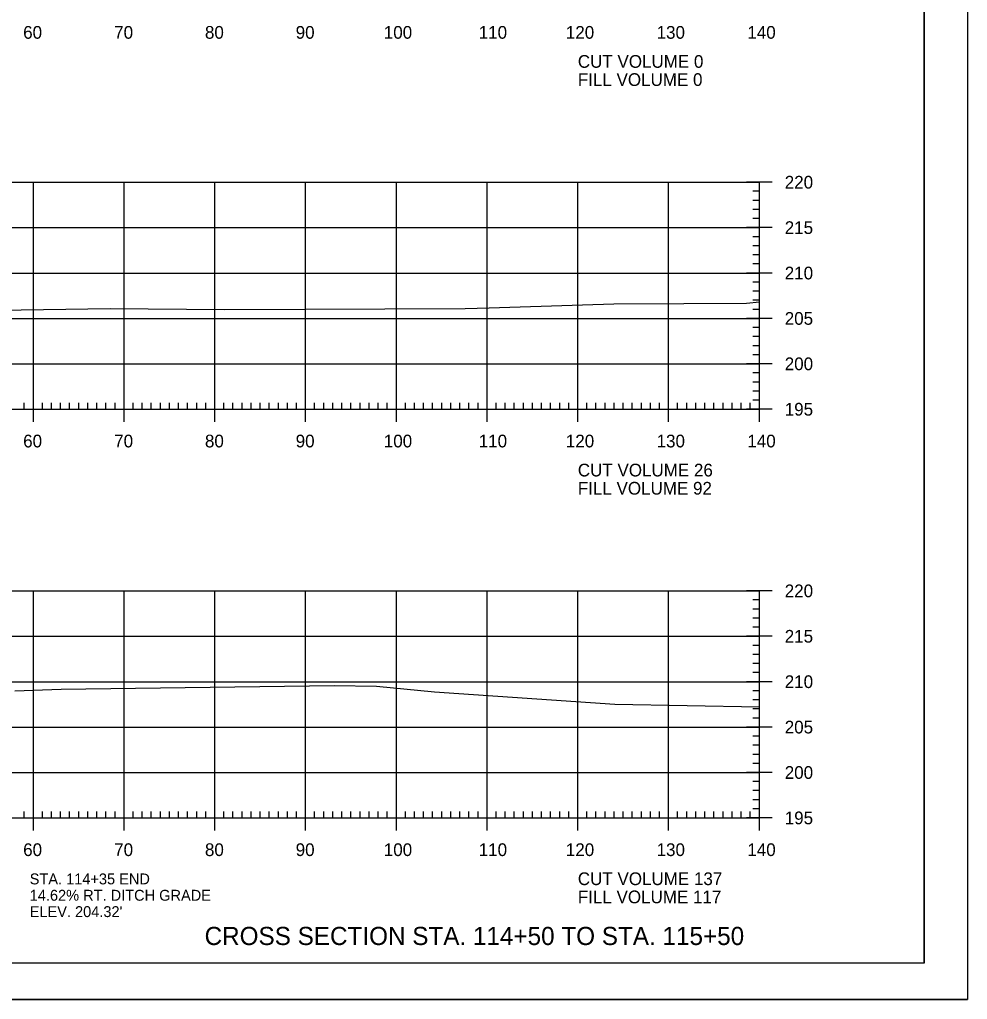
# Model space of a CAD drawing. Extents: x 1312042 to 1371461, y 379929 to 1834241.
# Drawn here: x 1371356.8 to 1371461.2, y 380142.3 to 380250.2 of the extents above; entities that cross this region are included whole.
import ezdxf

# ---------------------------------------------------------------- set-up
doc = ezdxf.new("R2010")
doc.units = 0
for name, color, linetype in [('R_Axis', 7, 'Continuous'), ('R_Axis Annot', 7, 'Continuous'), ('R_Border', 7, 'Continuous'), ('R_Draft', 7, 'Continuous'), ('R_Drive', 7, 'Continuous'), ('R_Exist Surface', 7, 'Continuous'), ('R_Grid', 7, 'Continuous'), ('R_No Plot', 7, 'Continuous')]:
    doc.layers.add(name, color=color, linetype=linetype)

msp = doc.modelspace()

# ---------------------------------------------------------------- linework, layer by layer
at = {"layer": 'R_Axis'}
for p, q in [((1371439.68, 380232.25), (1371436.88, 380232.25)), ((1371438.28, 380207.25), (1371438.28, 380232.25)), ((1371438.28, 380231.25), (1371437.58, 380231.25)), ((1371438.28, 380230.25), (1371437.58, 380230.25)), ((1371438.28, 380229.25), (1371437.58, 380229.25)), ((1371438.28, 380228.25), (1371437.58, 380228.25)), ((1371439.68, 380227.25), (1371436.88, 380227.25)), ((1371438.28, 380226.25), (1371437.58, 380226.25)), ((1371438.28, 380225.25), (1371437.58, 380225.25)), ((1371438.28, 380224.25), (1371437.58, 380224.25)), ((1371438.28, 380223.25), (1371437.58, 380223.25)), ((1371439.68, 380222.25), (1371436.88, 380222.25)), ((1371438.28, 380221.25), (1371437.58, 380221.25)), ((1371438.28, 380220.25), (1371437.58, 380220.25)), ((1371438.28, 380219.25), (1371437.58, 380219.25)), ((1371438.28, 380218.25), (1371437.58, 380218.25)), ((1371439.68, 380217.25), (1371436.88, 380217.25)), ((1371438.28, 380216.25), (1371437.58, 380216.25)), ((1371438.28, 380215.25), (1371437.58, 380215.25)), ((1371438.28, 380214.25), (1371437.58, 380214.25)), ((1371438.28, 380213.25), (1371437.58, 380213.25)), ((1371439.68, 380212.25), (1371436.88, 380212.25)), ((1371438.28, 380211.25), (1371437.58, 380211.25)), ((1371438.28, 380210.25), (1371437.58, 380210.25)), ((1371438.28, 380209.25), (1371437.58, 380209.25)), ((1371357.28, 380207.25), (1371357.28, 380207.95)), ((1371358.28, 380205.85), (1371358.28, 380208.65)), ((1371359.28, 380207.25), (1371359.28, 380207.95)), ((1371360.28, 380207.25), (1371360.28, 380207.95)), ((1371361.28, 380207.25), (1371361.28, 380207.95)), ((1371362.28, 380207.25), (1371362.28, 380207.95)), ((1371363.28, 380207.25), (1371363.28, 380207.95)), ((1371364.28, 380207.25), (1371364.28, 380207.95)), ((1371365.28, 380207.25), (1371365.28, 380207.95)), ((1371366.28, 380207.25), (1371366.28, 380207.95)), ((1371367.28, 380207.25), (1371367.28, 380207.95)), ((1371368.28, 380205.85), (1371368.28, 380208.65)), ((1371369.28, 380207.25), (1371369.28, 380207.95)), ((1371370.28, 380207.25), (1371370.28, 380207.95)), ((1371371.28, 380207.25), (1371371.28, 380207.95)), ((1371372.28, 380207.25), (1371372.28, 380207.95)), ((1371373.28, 380207.25), (1371373.28, 380207.95)), ((1371374.28, 380207.25), (1371374.28, 380207.95)), ((1371375.28, 380207.25), (1371375.28, 380207.95)), ((1371376.28, 380207.25), (1371376.28, 380207.95)), ((1371377.28, 380207.25), (1371377.28, 380207.95)), ((1371378.28, 380205.85), (1371378.28, 380208.65)), ((1371379.28, 380207.25), (1371379.28, 380207.95)), ((1371380.28, 380207.25), (1371380.28, 380207.95)), ((1371381.28, 380207.25), (1371381.28, 380207.95)), ((1371382.28, 380207.25), (1371382.28, 380207.95)), ((1371383.28, 380207.25), (1371383.28, 380207.95)), ((1371384.28, 380207.25), (1371384.28, 380207.95)), ((1371385.28, 380207.25), (1371385.28, 380207.95)), ((1371386.28, 380207.25), (1371386.28, 380207.95)), ((1371387.28, 380207.25), (1371387.28, 380207.95)), ((1371388.28, 380205.85), (1371388.28, 380208.65)), ((1371389.28, 380207.25), (1371389.28, 380207.95)), ((1371390.28, 380207.25), (1371390.28, 380207.95)), ((1371391.28, 380207.25), (1371391.28, 380207.95)), ((1371392.28, 380207.25), (1371392.28, 380207.95)), ((1371393.28, 380207.25), (1371393.28, 380207.95)), ((1371394.28, 380207.25), (1371394.28, 380207.95)), ((1371395.28, 380207.25), (1371395.28, 380207.95)), ((1371396.28, 380207.25), (1371396.28, 380207.95)), ((1371397.28, 380207.25), (1371397.28, 380207.95)), ((1371398.28, 380205.85), (1371398.28, 380208.65)), ((1371399.28, 380207.25), (1371399.28, 380207.95)), ((1371400.28, 380207.25), (1371400.28, 380207.95)), ((1371401.28, 380207.25), (1371401.28, 380207.95)), ((1371402.28, 380207.25), (1371402.28, 380207.95)), ((1371403.28, 380207.25), (1371403.28, 380207.95)), ((1371404.28, 380207.25), (1371404.28, 380207.95)), ((1371405.28, 380207.25), (1371405.28, 380207.95)), ((1371406.28, 380207.25), (1371406.28, 380207.95)), ((1371407.28, 380207.25), (1371407.28, 380207.95)), ((1371408.28, 380205.85), (1371408.28, 380208.65)), ((1371409.28, 380207.25), (1371409.28, 380207.95)), ((1371410.28, 380207.25), (1371410.28, 380207.95)), ((1371411.28, 380207.25), (1371411.28, 380207.95)), ((1371412.28, 380207.25), (1371412.28, 380207.95)), ((1371413.28, 380207.25), (1371413.28, 380207.95)), ((1371414.28, 380207.25), (1371414.28, 380207.95)), ((1371415.28, 380207.25), (1371415.28, 380207.95)), ((1371416.28, 380207.25), (1371416.28, 380207.95)), ((1371417.28, 380207.25), (1371417.28, 380207.95)), ((1371418.28, 380205.85), (1371418.28, 380208.65)), ((1371419.28, 380207.25), (1371419.28, 380207.95)), ((1371420.28, 380207.25), (1371420.28, 380207.95)), ((1371421.28, 380207.25), (1371421.28, 380207.95)), ((1371422.28, 380207.25), (1371422.28, 380207.95)), ((1371423.28, 380207.25), (1371423.28, 380207.95)), ((1371424.28, 380207.25), (1371424.28, 380207.95)), ((1371425.28, 380207.25), (1371425.28, 380207.95)), ((1371426.28, 380207.25), (1371426.28, 380207.95)), ((1371427.28, 380207.25), (1371427.28, 380207.95)), ((1371428.28, 380205.85), (1371428.28, 380208.65)), ((1371429.28, 380207.25), (1371429.28, 380207.95)), ((1371430.28, 380207.25), (1371430.28, 380207.95)), ((1371431.28, 380207.25), (1371431.28, 380207.95)), ((1371432.28, 380207.25), (1371432.28, 380207.95)), ((1371433.28, 380207.25), (1371433.28, 380207.95)), ((1371434.28, 380207.25), (1371434.28, 380207.95)), ((1371435.28, 380207.25), (1371435.28, 380207.95)), ((1371436.28, 380207.25), (1371436.28, 380207.95)), ((1371437.28, 380207.25), (1371437.28, 380207.95)), ((1371438.28, 380208.25), (1371437.58, 380208.25)), ((1371438.28, 380205.85), (1371438.28, 380208.65)), ((1371158.28, 380207.25), (1371438.28, 380207.25)), ((1371439.68, 380207.25), (1371436.88, 380207.25)), ((1371439.68, 380187.25), (1371436.88, 380187.25)), ((1371438.28, 380162.25), (1371438.28, 380187.25)), ((1371438.28, 380186.25), (1371437.58, 380186.25)), ((1371438.28, 380185.25), (1371437.58, 380185.25)), ((1371438.28, 380184.25), (1371437.58, 380184.25)), ((1371438.28, 380183.25), (1371437.58, 380183.25)), ((1371439.68, 380182.25), (1371436.88, 380182.25)), ((1371438.28, 380181.25), (1371437.58, 380181.25)), ((1371438.28, 380180.25), (1371437.58, 380180.25)), ((1371438.28, 380179.25), (1371437.58, 380179.25)), ((1371438.28, 380178.25), (1371437.58, 380178.25)), ((1371439.68, 380177.25), (1371436.88, 380177.25)), ((1371438.28, 380176.25), (1371437.58, 380176.25)), ((1371438.28, 380175.25), (1371437.58, 380175.25)), ((1371438.28, 380174.25), (1371437.58, 380174.25)), ((1371438.28, 380173.25), (1371437.58, 380173.25)), ((1371439.68, 380172.25), (1371436.88, 380172.25)), ((1371438.28, 380171.25), (1371437.58, 380171.25)), ((1371438.28, 380170.25), (1371437.58, 380170.25)), ((1371438.28, 380169.25), (1371437.58, 380169.25)), ((1371438.28, 380168.25), (1371437.58, 380168.25)), ((1371439.68, 380167.25), (1371436.88, 380167.25)), ((1371438.28, 380166.25), (1371437.58, 380166.25)), ((1371438.28, 380165.25), (1371437.58, 380165.25)), ((1371358.28, 380160.85), (1371358.28, 380163.65)), ((1371368.28, 380160.85), (1371368.28, 380163.65)), ((1371378.28, 380160.85), (1371378.28, 380163.65)), ((1371388.28, 380160.85), (1371388.28, 380163.65)), ((1371398.28, 380160.85), (1371398.28, 380163.65)), ((1371408.28, 380160.85), (1371408.28, 380163.65)), ((1371418.28, 380160.85), (1371418.28, 380163.65)), ((1371428.28, 380160.85), (1371428.28, 380163.65)), ((1371438.28, 380164.25), (1371437.58, 380164.25)), ((1371438.28, 380160.85), (1371438.28, 380163.65)), ((1371357.28, 380162.25), (1371357.28, 380162.95)), ((1371359.28, 380162.25), (1371359.28, 380162.95)), ((1371360.28, 380162.25), (1371360.28, 380162.95)), ((1371361.28, 380162.25), (1371361.28, 380162.95)), ((1371362.28, 380162.25), (1371362.28, 380162.95)), ((1371363.28, 380162.25), (1371363.28, 380162.95)), ((1371364.28, 380162.25), (1371364.28, 380162.95)), ((1371365.28, 380162.25), (1371365.28, 380162.95)), ((1371366.28, 380162.25), (1371366.28, 380162.95)), ((1371367.28, 380162.25), (1371367.28, 380162.95)), ((1371369.28, 380162.25), (1371369.28, 380162.95)), ((1371370.28, 380162.25), (1371370.28, 380162.95)), ((1371371.28, 380162.25), (1371371.28, 380162.95)), ((1371372.28, 380162.25), (1371372.28, 380162.95)), ((1371373.28, 380162.25), (1371373.28, 380162.95)), ((1371374.28, 380162.25), (1371374.28, 380162.95)), ((1371375.28, 380162.25), (1371375.28, 380162.95)), ((1371376.28, 380162.25), (1371376.28, 380162.95)), ((1371377.28, 380162.25), (1371377.28, 380162.95)), ((1371379.28, 380162.25), (1371379.28, 380162.95)), ((1371380.28, 380162.25), (1371380.28, 380162.95)), ((1371381.28, 380162.25), (1371381.28, 380162.95)), ((1371382.28, 380162.25), (1371382.28, 380162.95)), ((1371383.28, 380162.25), (1371383.28, 380162.95)), ((1371384.28, 380162.25), (1371384.28, 380162.95)), ((1371385.28, 380162.25), (1371385.28, 380162.95)), ((1371386.28, 380162.25), (1371386.28, 380162.95)), ((1371387.28, 380162.25), (1371387.28, 380162.95)), ((1371389.28, 380162.25), (1371389.28, 380162.95)), ((1371390.28, 380162.25), (1371390.28, 380162.95)), ((1371391.28, 380162.25), (1371391.28, 380162.95)), ((1371392.28, 380162.25), (1371392.28, 380162.95)), ((1371393.28, 380162.25), (1371393.28, 380162.95)), ((1371394.28, 380162.25), (1371394.28, 380162.95)), ((1371395.28, 380162.25), (1371395.28, 380162.95)), ((1371396.28, 380162.25), (1371396.28, 380162.95)), ((1371397.28, 380162.25), (1371397.28, 380162.95)), ((1371399.28, 380162.25), (1371399.28, 380162.95)), ((1371400.28, 380162.25), (1371400.28, 380162.95)), ((1371401.28, 380162.25), (1371401.28, 380162.95)), ((1371402.28, 380162.25), (1371402.28, 380162.95)), ((1371403.28, 380162.25), (1371403.28, 380162.95)), ((1371404.28, 380162.25), (1371404.28, 380162.95)), ((1371405.28, 380162.25), (1371405.28, 380162.95)), ((1371406.28, 380162.25), (1371406.28, 380162.95)), ((1371407.28, 380162.25), (1371407.28, 380162.95)), ((1371409.28, 380162.25), (1371409.28, 380162.95)), ((1371410.28, 380162.25), (1371410.28, 380162.95)), ((1371411.28, 380162.25), (1371411.28, 380162.95)), ((1371412.28, 380162.25), (1371412.28, 380162.95)), ((1371413.28, 380162.25), (1371413.28, 380162.95)), ((1371414.28, 380162.25), (1371414.28, 380162.95)), ((1371415.28, 380162.25), (1371415.28, 380162.95)), ((1371416.28, 380162.25), (1371416.28, 380162.95)), ((1371417.28, 380162.25), (1371417.28, 380162.95)), ((1371419.28, 380162.25), (1371419.28, 380162.95)), ((1371420.28, 380162.25), (1371420.28, 380162.95)), ((1371421.28, 380162.25), (1371421.28, 380162.95)), ((1371422.28, 380162.25), (1371422.28, 380162.95)), ((1371423.28, 380162.25), (1371423.28, 380162.95)), ((1371424.28, 380162.25), (1371424.28, 380162.95)), ((1371425.28, 380162.25), (1371425.28, 380162.95)), ((1371426.28, 380162.25), (1371426.28, 380162.95)), ((1371427.28, 380162.25), (1371427.28, 380162.95)), ((1371429.28, 380162.25), (1371429.28, 380162.95)), ((1371430.28, 380162.25), (1371430.28, 380162.95)), ((1371431.28, 380162.25), (1371431.28, 380162.95)), ((1371432.28, 380162.25), (1371432.28, 380162.95)), ((1371433.28, 380162.25), (1371433.28, 380162.95)), ((1371434.28, 380162.25), (1371434.28, 380162.95)), ((1371435.28, 380162.25), (1371435.28, 380162.95)), ((1371436.28, 380162.25), (1371436.28, 380162.95)), ((1371437.28, 380162.25), (1371437.28, 380162.95)), ((1371438.28, 380163.25), (1371437.58, 380163.25)), ((1371158.28, 380162.25), (1371438.28, 380162.25)), ((1371439.68, 380162.25), (1371436.88, 380162.25))]:
    msp.add_line(p, q, dxfattribs=at)
at = {"layer": 'R_Border'}
for q in [(1371456.46, 380351.71), (1371140.28, 380146.25)]:
    msp.add_line((1371456.46, 380146.25), q, dxfattribs=at)
at = {"layer": 'R_Exist Surface'}
for points in [[(1371352.03, 380218.14), (1371366.76, 380218.33), (1371379.34, 380218.24), (1371405.86, 380218.34), (1371408.52, 380218.42), (1371418.79, 380218.73), (1371422.23, 380218.84), (1371429.97, 380218.88), (1371436.88, 380218.92), (1371438.28, 380219.06)], [(1371356.23, 380176.24), (1371361.36, 380176.42), (1371391.44, 380176.83), (1371396.11, 380176.77), (1371402.47, 380176.15), (1371402.47, 380176.15), (1371422.37, 380174.76), (1371438.28, 380174.47)]]:
    msp.add_lwpolyline(points, dxfattribs=at)
at = {"layer": 'R_Grid'}
for p, q in [((1371158.28, 380232.25), (1371438.28, 380232.25)), ((1371358.28, 380207.25), (1371358.28, 380232.25)), ((1371368.28, 380207.25), (1371368.28, 380232.25)), ((1371378.28, 380207.25), (1371378.28, 380232.25)), ((1371388.28, 380207.25), (1371388.28, 380232.25)), ((1371398.28, 380207.25), (1371398.28, 380232.25)), ((1371408.28, 380207.25), (1371408.28, 380232.25)), ((1371418.28, 380207.25), (1371418.28, 380232.25)), ((1371428.28, 380207.25), (1371428.28, 380232.25)), ((1371438.28, 380207.25), (1371438.28, 380232.25)), ((1371158.28, 380227.25), (1371438.28, 380227.25)), ((1371158.28, 380222.25), (1371438.28, 380222.25)), ((1371158.28, 380217.25), (1371438.28, 380217.25)), ((1371158.28, 380212.25), (1371438.28, 380212.25)), ((1371158.28, 380207.25), (1371438.28, 380207.25)), ((1371158.28, 380187.25), (1371438.28, 380187.25)), ((1371358.28, 380162.25), (1371358.28, 380187.25)), ((1371368.28, 380162.25), (1371368.28, 380187.25)), ((1371378.28, 380162.25), (1371378.28, 380187.25)), ((1371388.28, 380162.25), (1371388.28, 380187.25)), ((1371398.28, 380162.25), (1371398.28, 380187.25)), ((1371408.28, 380162.25), (1371408.28, 380187.25)), ((1371418.28, 380162.25), (1371418.28, 380187.25)), ((1371428.28, 380162.25), (1371428.28, 380187.25)), ((1371438.28, 380162.25), (1371438.28, 380187.25)), ((1371158.28, 380182.25), (1371438.28, 380182.25)), ((1371158.28, 380177.25), (1371438.28, 380177.25)), ((1371158.28, 380172.25), (1371438.28, 380172.25)), ((1371158.28, 380167.25), (1371438.28, 380167.25)), ((1371158.28, 380162.25), (1371438.28, 380162.25))]:
    msp.add_line(p, q, dxfattribs=at)
at = {"layer": 'R_No Plot'}
msp.add_line((1371127.88, 380142.27), (1371461.21, 380142.27), dxfattribs=at)
for points in [[(1371127.87, 380355.6), (1371461.21, 380355.6), (1371461.21, 380142.26), (1371127.87, 380142.26)], [(1371374.2, 380351.71), (1371374.2, 380341.83), (1371409.93, 380341.83), (1371409.93, 380338.91), (1371433.13, 380338.91), (1371433.13, 380314.57), (1371456.46, 380314.57), (1371456.46, 380146.25), (1371140.28, 380146.25), (1371140.28, 380351.71)]]:
    msp.add_lwpolyline(points, close=True, dxfattribs=at)

# ---------------------------------------------------------------- texts
at = {"layer": 'R_Axis Annot'}
for s, p in [('60', (1371357.16, 380248.05)), ('70', (1371367.19, 380248.05)), ('80', (1371377.19, 380248.05)), ('90', (1371387.19, 380248.05)), ('100', (1371396.9, 380248.05)), ('110', (1371407.36, 380248.05)), ('120', (1371416.96, 380248.05)), ('130', (1371426.96, 380248.05)), ('140', (1371436.96, 380248.05)), ('CUT VOLUME 0', (1371418.28, 380244.85)), ('FILL VOLUME 0', (1371418.28, 380242.85)), ('220', (1371441.08, 380231.55)), ('215', (1371441.08, 380226.55)), ('210', (1371441.08, 380221.55)), ('205', (1371441.08, 380216.55)), ('200', (1371441.08, 380211.55)), ('195', (1371441.08, 380206.55)), ('60', (1371357.16, 380203.05)), ('70', (1371367.19, 380203.05)), ('80', (1371377.19, 380203.05)), ('90', (1371387.19, 380203.05)), ('100', (1371396.9, 380203.05)), ('110', (1371407.36, 380203.05)), ('120', (1371416.96, 380203.05)), ('130', (1371426.96, 380203.05)), ('140', (1371436.96, 380203.05)), ('CUT VOLUME 26', (1371418.28, 380199.85)), ('FILL VOLUME 92', (1371418.28, 380197.85)), ('220', (1371441.08, 380186.55)), ('215', (1371441.08, 380181.55)), ('210', (1371441.08, 380176.55)), ('205', (1371441.08, 380171.55)), ('200', (1371441.08, 380166.55)), ('195', (1371441.08, 380161.55)), ('60', (1371357.16, 380158.05)), ('70', (1371367.19, 380158.05)), ('80', (1371377.19, 380158.05)), ('90', (1371387.19, 380158.05)), ('100', (1371396.9, 380158.05)), ('110', (1371407.36, 380158.05)), ('120', (1371416.96, 380158.05)), ('130', (1371426.96, 380158.05)), ('140', (1371436.96, 380158.05)), ('CUT VOLUME 137', (1371418.28, 380154.85)), ('FILL VOLUME 117', (1371418.28, 380152.85))]:
    msp.add_text(s, height=1.4, dxfattribs=at).set_placement(p)
at = {"layer": 'R_Draft'}
msp.add_text('CROSS SECTION STA. 114+50 TO STA. 115+50', height=2, dxfattribs=at).set_placement((1371377.15, 380148.25))
at = {"layer": 'R_Drive'}
for s, p in [('STA. 114+35 END', (1371357.88, 380154.93)), ('14.62% RT. DITCH GRADE', (1371357.88, 380153.13)), ("ELEV. 204.32'", (1371357.88, 380151.33))]:
    msp.add_text(s, height=1.2, dxfattribs=at).set_placement(p)

doc.saveas('drawing.dxf')
